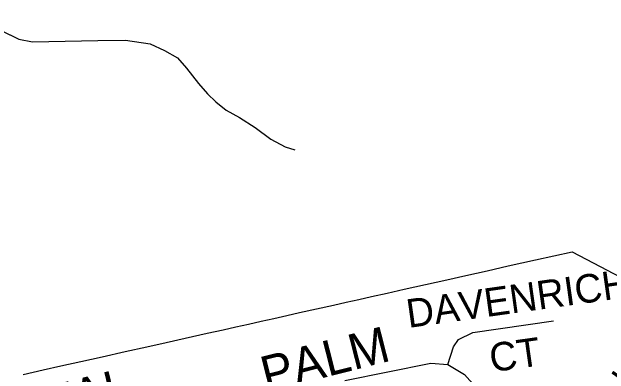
# Model space of a CAD drawing. Extents: x 586326 to 623965, y 4819854 to 4857850.
# Drawn here: x 597382.2 to 597800.5, y 4843142.3 to 4843396.1 of the extents above; entities that cross this region are included whole.
import ezdxf

# ---------------------------------------------------------------- set-up
doc = ezdxf.new("R2010")
doc.units = 0
for name, color, linetype in [('Minor Rd Lbls', 7, 'Continuous'), ('Minor Rds', 7, 'Continuous'), ('Park Outlines', 7, 'Continuous'), ('Private Rds', 7, 'Continuous')]:
    doc.layers.add(name, color=color, linetype=linetype)

msp = doc.modelspace()

# ---------------------------------------------------------------- linework, layer by layer
at = {"layer": 'Minor Rds'}
for points in [[(597687.49, 4843149.03), (597691.49, 4843161.33), (597694.98, 4843166.61), (597705.08, 4843171.41), (597761.53, 4843179.5)], [(597615.43, 4843137.88), (597675.65, 4843149.99), (597687.49, 4843149.03)], [(597687.49, 4843149.03), (597699.17, 4843141.92), (597707.04, 4843133.32), (597749.05, 4843062.83), (597753.23, 4843055.99)]]:
    msp.add_lwpolyline(points, dxfattribs=at)
at = {"layer": 'Park Outlines'}
msp.add_lwpolyline([(597390.16, 4843142.05), (597404.08, 4843145.17), (597416.45, 4843147.94), (597430.37, 4843151.05), (597445.53, 4843154.44), (597461.59, 4843158.03), (597476.75, 4843161.43), (597490.19, 4843164.43), (597503.61, 4843167.44), (597519.08, 4843170.9), (597530.08, 4843173.36), (597539, 4843175.35), (597547.92, 4843177.35), (597556.84, 4843179.34), (597565.76, 4843181.34), (597574.68, 4843183.34), (597583.6, 4843185.33), (597595.5, 4843187.99), (597607.39, 4843190.65), (597616.31, 4843192.65), (597625.23, 4843194.65), (597634.15, 4843196.64), (597645.15, 4843199.1), (597657.05, 4843201.76), (597671.92, 4843205.09), (597686.78, 4843208.42), (597700.16, 4843211.41), (597715.03, 4843214.74), (597729.9, 4843218.06), (597748.93, 4843222.32), (597774.63, 4843228.07), (597784.58, 4843222.81), (597813.42, 4843207.56)], dxfattribs=at)
at = {"layer": 'Private Rds'}
msp.add_lwpolyline([(597356.73, 4843396.15), (597374.68, 4843383.12), (597387.06, 4843377.16), (597396.54, 4843375.09), (597442.43, 4843376.05), (597461.8, 4843376.34), (597478.96, 4843373.73), (597489, 4843369.15), (597498.3, 4843363.9), (597504.39, 4843356.82), (597512.8, 4843346.04), (597519.12, 4843338.71), (597524.95, 4843333.21), (597532.2, 4843327.36), (597541.6, 4843322.03), (597552.7, 4843315.03), (597563.66, 4843306.97), (597573.63, 4843301.52), (597580.27, 4843299.52)], dxfattribs=at)

# ---------------------------------------------------------------- texts
at = {"layer": 'Minor Rd Lbls'}
for s, height, rotation, p in [('DAVENRICH', 19.998, 7.9696, (597659.98, 4843174.59)), ('PALM', 25.002, 14.2645, (597560.31, 4843129.41)), ('CT', 19.998, 7.9696, (597718.18, 4843143.52)), ('RHINE', 19.998, 54.7133, (597783.29, 4843081.44)), ('ROYAL', 25.002, 13.8697, (597358.2, 4843095.87))]:
    msp.add_text(s, height=height, rotation=rotation, dxfattribs=at).set_placement(p)

doc.saveas('drawing.dxf')
